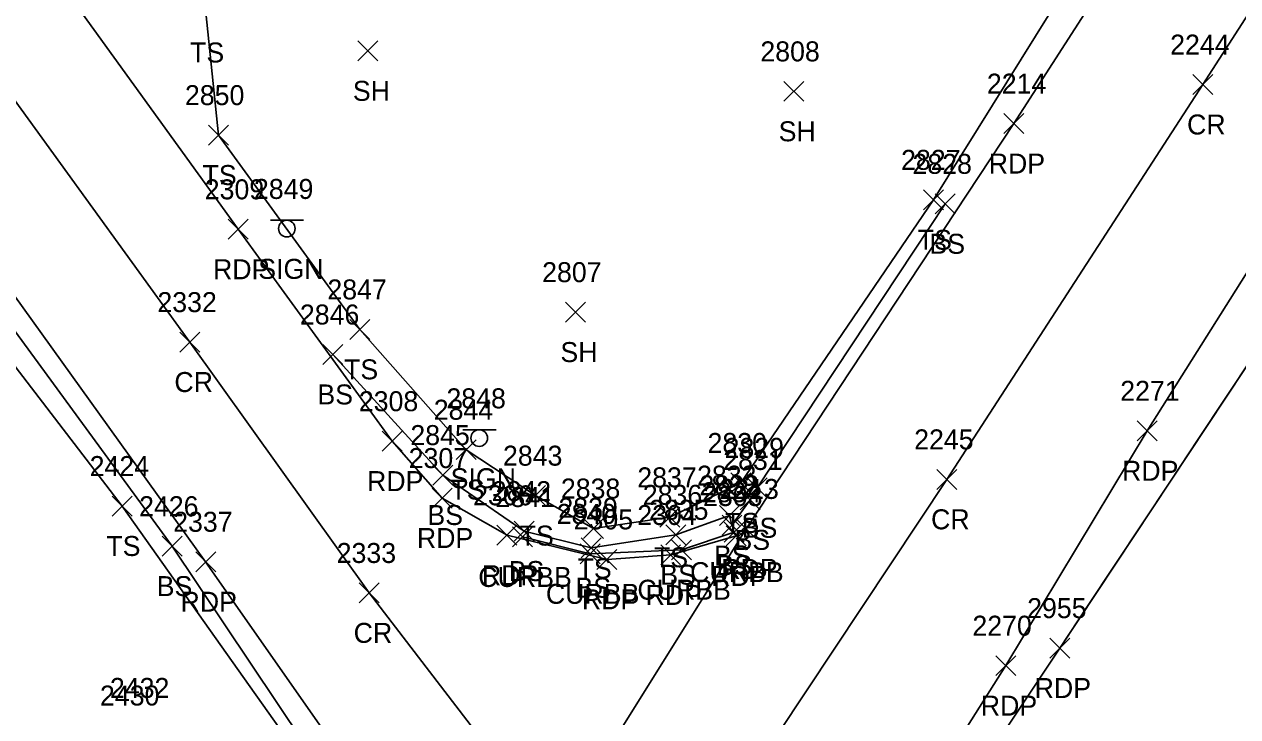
# Model space of a CAD drawing. Extents: x 1638344 to 1639591, y 610835 to 612202.
# Drawn here: x 1639077.4 to 1639198.8, y 611313 to 611382.3 of the extents above; entities that cross this region are included whole.
import ezdxf

# ---------------------------------------------------------------- set-up
doc = ezdxf.new("R2010")
doc.units = 0
for name, color, linetype in [('L_A', 7, 'Continuous'), ('L_I', 7, 'Continuous'), ('L_TIC', 7, 'Continuous'), ('LELB', 7, 'Continuous'), ('LSOGP', 7, 'Continuous'), ('P_A', 7, 'Continuous'), ('P_I', 7, 'Continuous'), ('P_TIC', 7, 'Continuous'), ('PET', 7, 'Continuous'), ('PRC', 7, 'Continuous'), ('R_A', 7, 'Continuous'), ('R_I', 7, 'Continuous'), ('R_TIC', 7, 'Continuous'), ('RC', 7, 'Continuous'), ('S_A', 7, 'Continuous'), ('S_I', 7, 'Continuous'), ('SSGN', 7, 'Continuous')]:
    doc.layers.add(name, color=color, linetype=linetype)

msp = doc.modelspace()

# ---------------------------------------------------------------- linework, layer by layer
at = {"layer": 'L_TIC'}
for points in [[(1639110.76, 611378.64), (1639112.76, 611380.64)], [(1639112.76, 611378.64), (1639110.76, 611380.64)], [(1639153.39, 611374.59), (1639155.39, 611376.59)], [(1639155.39, 611374.59), (1639153.39, 611376.59)], [(1639095.79, 611370.21), (1639097.79, 611372.21)], [(1639097.79, 611370.21), (1639095.79, 611372.21)], [(1639167.4, 611363.73), (1639169.4, 611365.73)], [(1639169.4, 611363.73), (1639167.4, 611365.73)], [(1639168.54, 611363.34), (1639170.54, 611365.34)], [(1639170.54, 611363.34), (1639168.54, 611365.34)], [(1639131.54, 611352.49), (1639133.54, 611354.49)], [(1639133.54, 611352.49), (1639131.54, 611354.49)], [(1639109.96, 611350.76), (1639111.96, 611352.76)], [(1639111.96, 611350.76), (1639109.96, 611352.76)], [(1639107.26, 611348.25), (1639109.26, 611350.25)], [(1639109.26, 611348.25), (1639107.26, 611350.25)], [(1639120.61, 611338.72), (1639122.61, 611340.72)], [(1639122.61, 611338.72), (1639120.61, 611340.72)], [(1639118.27, 611336.18), (1639120.27, 611338.18)], [(1639120.27, 611336.18), (1639118.27, 611338.18)], [(1639148.11, 611335.39), (1639150.11, 611337.39)], [(1639150.11, 611335.39), (1639148.11, 611337.39)], [(1639127.54, 611334.12), (1639129.54, 611336.12)], [(1639129.54, 611334.12), (1639127.54, 611336.12)], [(1639149.74, 611334.9), (1639151.74, 611336.9)], [(1639151.74, 611334.9), (1639149.74, 611336.9)], [(1639086.16, 611333.08), (1639088.16, 611335.08)], [(1639088.16, 611333.08), (1639086.16, 611335.08)], [(1639149.02, 611333.69), (1639151.02, 611335.69)], [(1639151.02, 611333.69), (1639149.02, 611335.69)], [(1639140.99, 611331.95), (1639142.99, 611333.95)], [(1639142.99, 611331.95), (1639140.99, 611333.95)], [(1639146.97, 611332.12), (1639148.97, 611334.12)], [(1639148.97, 611332.12), (1639146.97, 611334.12)], [(1639126.41, 611330.57), (1639128.41, 611332.57)], [(1639128.41, 611330.57), (1639126.41, 611332.57)], [(1639133.34, 611330.83), (1639135.34, 611332.83)], [(1639135.34, 611330.83), (1639133.34, 611332.83)], [(1639147.21, 611331.15), (1639149.2, 611333.15)], [(1639149.2, 611331.15), (1639147.21, 611333.15)], [(1639141.59, 611330.2), (1639143.59, 611332.2)], [(1639143.59, 611330.2), (1639141.59, 611332.2)], [(1639091.17, 611329.06), (1639093.16, 611331.06)], [(1639093.16, 611329.06), (1639091.17, 611331.06)], [(1639133.1, 611328.9), (1639135.1, 611330.9)], [(1639135.1, 611328.9), (1639133.1, 611330.9)]]:
    msp.add_lwpolyline(points, dxfattribs=at)
at = {"layer": 'LELB'}
for points in [[(1639184.51, 611390.62), (1639168.4, 611364.73), (1639149.11, 611336.39), (1639141.99, 611332.95), (1639134.34, 611331.83), (1639128.54, 611335.12), (1639121.61, 611339.72), (1639110.96, 611351.76), (1639096.79, 611371.21), (1639095.54, 611383.48), (1639101.8, 611394.14), (1639116.54, 611418.41), (1639131.91, 611444.98), (1639113.36, 611469.05), (1639093.12, 611490.67), (1639071.05, 611509.19), (1639055.5, 611526.42)], [(1639107.91, 611306.54), (1639092.17, 611330.06), (1639069.35, 611361.19), (1639057.96, 611376.85)], [(1639107.51, 611305.33), (1639087.16, 611334.08), (1639058.16, 611371.88)], [(1639169.54, 611364.33), (1639150.74, 611335.9), (1639150.02, 611334.69), (1639148.21, 611332.15), (1639147.97, 611333.12), (1639142.59, 611331.2), (1639134.1, 611329.9), (1639127.41, 611331.57), (1639119.27, 611337.18), (1639108.26, 611349.25)]]:
    msp.add_lwpolyline(points, dxfattribs=at)
at = {"layer": 'LSOGP'}
msp.add_lwpolyline([(1639176.23, 611312.66), (1639181.02, 611319.86), (1639183.79, 611324.04), (1639186.56, 611328.22), (1639189.34, 611332.4), (1639192.11, 611336.58), (1639194.88, 611340.76), (1639197.65, 611344.93), (1639200.42, 611349.11)], dxfattribs=at)
at = {"layer": 'P_TIC'}
for points in [[(1639194.34, 611375.27), (1639196.34, 611377.27)], [(1639196.34, 611375.27), (1639194.34, 611377.27)], [(1639175.42, 611371.36), (1639177.42, 611373.36)], [(1639177.42, 611371.36), (1639175.42, 611373.36)], [(1639097.76, 611360.78), (1639099.76, 611362.78)], [(1639099.76, 611360.78), (1639097.76, 611362.78)], [(1639092.94, 611349.49), (1639094.94, 611351.49)], [(1639094.94, 611349.49), (1639092.94, 611351.49)], [(1639188.77, 611340.61), (1639190.77, 611342.61)], [(1639190.77, 611340.61), (1639188.77, 611342.61)], [(1639113.19, 611339.57), (1639115.19, 611341.57)], [(1639115.19, 611339.57), (1639113.19, 611341.57)], [(1639168.71, 611335.75), (1639170.71, 611337.75)], [(1639170.71, 611335.75), (1639168.71, 611337.75)], [(1639118.18, 611333.88), (1639120.18, 611335.88)], [(1639120.18, 611333.88), (1639118.18, 611335.88)], [(1639148.64, 611330.79), (1639150.64, 611332.79)], [(1639150.64, 611330.79), (1639148.64, 611332.79)], [(1639124.68, 611330.15), (1639126.68, 611332.15)], [(1639126.68, 611330.15), (1639124.68, 611332.15)], [(1639147.64, 611330.08), (1639149.64, 611332.08)], [(1639149.64, 611330.08), (1639147.64, 611332.08)], [(1639141.07, 611328.18), (1639143.07, 611330.18)], [(1639143.07, 611328.18), (1639141.07, 611330.18)], [(1639094.52, 611327.5), (1639096.52, 611329.5)], [(1639096.52, 611327.5), (1639094.52, 611329.5)], [(1639134.69, 611327.74), (1639136.69, 611329.74)], [(1639136.69, 611327.74), (1639134.69, 611329.74)], [(1639110.89, 611324.38), (1639112.89, 611326.38)], [(1639112.89, 611324.38), (1639110.89, 611326.38)], [(1639180.02, 611318.86), (1639182.02, 611320.86)], [(1639182.02, 611318.86), (1639180.02, 611320.86)], [(1639174.63, 611317.1), (1639176.63, 611319.1)], [(1639176.63, 611317.1), (1639174.63, 611319.1)]]:
    msp.add_lwpolyline(points, dxfattribs=at)
at = {"layer": 'PET'}
for points in [[(1639148.64, 611331.08), (1639142.07, 611329.18), (1639135.7, 611328.74), (1639125.69, 611331.15), (1639119.18, 611334.88), (1639114.19, 611340.57), (1639098.76, 611361.78), (1639080.32, 611387.34), (1639061.62, 611413.48), (1639039.15, 611444.22), (1639014.34, 611480.36), (1638988.41, 611516.9), (1638963.39, 611551.85), (1638935.46, 611588.7), (1638918.51, 611609.36), (1638899.73, 611630.86), (1638874.41, 611653.86), (1638846.55, 611674.47), (1638833.14, 611682.54), (1638823.86, 611689.16)], [(1639117.36, 611283.38), (1639114.12, 611301.89), (1639095.51, 611328.5), (1639070.51, 611363.26), (1639041.38, 611404.69), (1639011.58, 611446.4), (1638984.33, 611485.15), (1638954.17, 611527.5), (1638934.33, 611554.77), (1638918.88, 611575.58), (1638893.27, 611605.67), (1638868.12, 611629.84), (1638836.66, 611652.85), (1638812.43, 611667.64)], [(1638854.83, 610853.22), (1638885.37, 610909), (1638902.82, 610937.28), (1638929.33, 610982.56), (1638950.92, 611019.42), (1638971.29, 611051.92), (1639000.04, 611096.97), (1639023.57, 611133.7), (1639039.12, 611159.19), (1639064.62, 611197.79), (1639080.51, 611223.3), (1639114.23, 611277.34), (1639131.17, 611302.28), (1639149.64, 611331.79), (1639176.42, 611372.36), (1639193.48, 611398.88)], [(1639227.99, 611172.98), (1639228.32, 611174.39), (1639214.9, 611192.14), (1639202.86, 611208.11), (1639190.66, 611227), (1639183.08, 611239.21), (1639162.79, 611271), (1639160.92, 611274.86), (1639160.06, 611279.39), (1639160.11, 611285.35), (1639161.85, 611291.07), (1639181.02, 611319.86), (1639203.19, 611353.29), (1639219.74, 611378.25), (1639229.46, 611393.47)], [(1638878.4, 610839.82), (1638902.26, 610883.1), (1638925.76, 610925.07), (1638957.26, 610978.12), (1638978.73, 611014.12), (1639004.29, 611055.33), (1639040.97, 611112.29), (1639073.41, 611162.89), (1639102.56, 611207.56), (1639124.27, 611240.99), (1639140.69, 611264.29), (1639156.2, 611287.4), (1639175.63, 611318.1), (1639189.77, 611341.61), (1639219.88, 611389.38)]]:
    msp.add_lwpolyline(points, dxfattribs=at)
at = {"layer": 'PRC'}
for points in [[(1638818.79, 611678.84), (1638843.98, 611663.35), (1638876.44, 611637.39), (1638906.24, 611607.19), (1638934.14, 611573.69), (1638965.31, 611531.43), (1638998.82, 611484.34), (1639033.82, 611434.48), (1639068.01, 611386.3), (1639093.94, 611350.49), (1639111.89, 611325.38), (1639129.23, 611302.77)], [(1639222.36, 611418.19), (1639195.34, 611376.27), (1639169.71, 611336.75), (1639147.17, 611302.78), (1639120.59, 611261.17), (1639092.55, 611217.83), (1639063.71, 611172.41), (1639032.46, 611123.7), (1639004.79, 611080.3), (1638977.88, 611037.27), (1638950.44, 610992.13), (1638925.95, 610950.29), (1638900.28, 610905.37), (1638879.75, 610869.2), (1638867.14, 610846.08)]]:
    msp.add_lwpolyline(points, dxfattribs=at)
at = {"layer": 'R_TIC'}
for points in [[(1639147.44, 611330.46), (1639149.44, 611332.46)], [(1639149.44, 611330.46), (1639147.44, 611332.46)], [(1639126.23, 611329.99), (1639128.23, 611331.98)], [(1639128.23, 611329.99), (1639126.23, 611331.98)], [(1639133, 611328.29), (1639135, 611330.29)], [(1639135, 611328.29), (1639133, 611330.29)], [(1639142.16, 611328.7), (1639144.16, 611330.7)], [(1639144.16, 611328.7), (1639142.16, 611330.7)]]:
    msp.add_lwpolyline(points, dxfattribs=at)
at = {"layer": 'RC'}
msp.add_lwpolyline([(1639148.44, 611331.46), (1639143.16, 611329.7), (1639134, 611329.29), (1639127.23, 611330.98)], dxfattribs=at)
at = {"layer": 'SSGN'}
for p, q in [((1639101.99, 611362.68), (1639105.32, 611362.68)), ((1639103.64, 611361.85), (1639103.64, 611361.85)), ((1639121.25, 611341.71), (1639124.59, 611341.71)), ((1639122.9, 611340.88), (1639122.9, 611340.88))]:
    msp.add_line(p, q, dxfattribs=at)
for centre in [(1639103.64, 611361.85), (1639122.9, 611340.88)]:
    msp.add_circle(centre, 0.833, dxfattribs=at)

# ---------------------------------------------------------------- texts
at = {"layer": 'L_A'}
for s, p in [('TS', (1639093.95, 611378.48)), ('SH', (1639110.25, 611374.64)), ('SH', (1639152.88, 611370.59)), ('TS', (1639095.2, 611366.21)), ('TS', (1639166.81, 611359.73)), ('BS', (1639167.98, 611359.33)), ('SH', (1639131.03, 611348.49)), ('TS', (1639109.37, 611346.76)), ('BS', (1639106.7, 611344.25)), ('TS', (1639120.02, 611334.72)), ('BS', (1639117.71, 611332.18)), ('TS', (1639147.52, 611331.39)), ('BS', (1639149.18, 611330.9)), ('TS', (1639126.95, 611330.12)), ('BS', (1639148.46, 611329.69)), ('TS', (1639085.57, 611329.08)), ('TS', (1639140.4, 611327.95)), ('BS', (1639146.41, 611328.12)), ('TS', (1639132.75, 611326.83)), ('BS', (1639146.65, 611327.15)), ('BS', (1639125.85, 611326.57)), ('BS', (1639141.03, 611326.2)), ('BS', (1639090.61, 611325.06)), ('BS', (1639132.54, 611324.9))]:
    msp.add_text(s, height=2, dxfattribs=at).set_placement(p)
at = {"layer": 'L_I'}
for s, p in [('2808', (1639151.05, 611378.59)), ('2850', (1639093.44, 611374.21)), ('2827', (1639165.14, 611367.73)), ('2828', (1639166.28, 611367.33)), ('2807', (1639129.2, 611356.49)), ('2847', (1639107.7, 611354.76)), ('2846', (1639104.95, 611352.25)), ('2844', (1639118.35, 611342.72)), ('2845', (1639116.01, 611340.18)), ('2830', (1639145.76, 611339.39)), ('2829', (1639147.47, 611338.9)), ('2843', (1639125.28, 611338.12)), ('2831', (1639147.33, 611337.69)), ('2424', (1639083.9, 611337.08)), ('2837', (1639138.73, 611335.95)), ('2833', (1639144.71, 611336.12)), ('2842', (1639124.15, 611334.57)), ('2838', (1639131.08, 611334.83)), ('2836', (1639139.28, 611334.2)), ('2832', (1639144.95, 611335.15)), ('2426', (1639088.85, 611333.06)), ('2839', (1639130.83, 611332.9))]:
    msp.add_text(s, height=2, dxfattribs=at).set_placement(p)
at = {"layer": 'P_A'}
for s, p in [('CR', (1639193.77, 611371.27)), ('RDP', (1639173.91, 611367.36)), ('RDP', (1639096.25, 611356.78)), ('CR', (1639092.38, 611345.49)), ('RDP', (1639187.26, 611336.61)), ('RDP', (1639111.67, 611335.57)), ('CR', (1639168.14, 611331.75)), ('RDP', (1639116.66, 611329.88)), ('RDP', (1639147.13, 611326.79)), ('RDP', (1639123.17, 611326.15)), ('RDP', (1639146.13, 611326.08)), ('RDP', (1639093, 611323.5)), ('RDP', (1639133.18, 611323.74)), ('RDP', (1639139.56, 611324.18)), ('CR', (1639110.33, 611320.38)), ('RDP', (1639178.51, 611314.86)), ('RDP', (1639173.12, 611313.1))]:
    msp.add_text(s, height=2, dxfattribs=at).set_placement(p)
at = {"layer": 'P_I'}
for s, p in [('2244', (1639192.08, 611379.27)), ('2214', (1639173.73, 611375.36)), ('2309', (1639095.42, 611364.78)), ('2332', (1639090.68, 611353.49)), ('2271', (1639187.08, 611344.61)), ('2308', (1639110.85, 611343.57)), ('2245', (1639166.45, 611339.75)), ('2307', (1639115.84, 611337.88)), ('2306', (1639122.29, 611334.15)), ('2303', (1639145.31, 611334.08)), ('2213', (1639146.95, 611334.79)), ('2305', (1639132.36, 611331.74)), ('2304', (1639138.73, 611332.18)), ('2337', (1639092.26, 611331.5)), ('2333', (1639108.63, 611328.38)), ('2955', (1639177.76, 611322.86)), ('2270', (1639172.28, 611321.1))]:
    msp.add_text(s, height=2, dxfattribs=at).set_placement(p)
at = {"layer": 'R_A'}
for p in [(1639122.81, 611325.98), (1639144.02, 611326.46), (1639138.74, 611324.7), (1639129.58, 611324.29)]:
    msp.add_text('CURBB', height=2, dxfattribs=at).set_placement(p)
at = {"layer": 'R_I'}
for s, p in [('2834', (1639145.18, 611334.46)), ('2841', (1639124.53, 611333.98)), ('2840', (1639130.66, 611332.29)), ('2835', (1639139.9, 611332.7)), ('2432', (1639085.93, 611314.87))]:
    msp.add_text(s, height=2, dxfattribs=at).set_placement(p)
at = {"layer": 'S_A'}
for p in [(1639100.78, 611356.82), (1639120.04, 611335.86)]:
    msp.add_text('SIGN', height=2, dxfattribs=at).set_placement(p)
at = {"layer": 'S_I'}
for s, p in [('2849', (1639100.35, 611364.82)), ('2848', (1639119.62, 611343.86)), ('2430', (1639084.93, 611314.11))]:
    msp.add_text(s, height=2, dxfattribs=at).set_placement(p)

doc.saveas('drawing.dxf')
